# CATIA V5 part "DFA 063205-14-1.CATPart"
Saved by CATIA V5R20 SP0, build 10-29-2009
Part number: DFA 063205-14-1
Revision: ANY
Definition: UNKNOWN
Nomenclature: DFA 063205-14-1
Source: Unknown
Bounding box of the stored display mesh (mm): x -3 to 3, y -9.95 to 10.05, z -3 to 3
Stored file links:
  C:\Users\Utente\Desktop\IO LAVORO\3D X SITO CF\CUMSA\3D files FA\FA 063205-21\DFA 063205-14-1.CATPart

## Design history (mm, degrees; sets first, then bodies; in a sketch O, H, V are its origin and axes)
Body1 "Cortar-Extruir5" (main body)
  Solid1: solid without history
